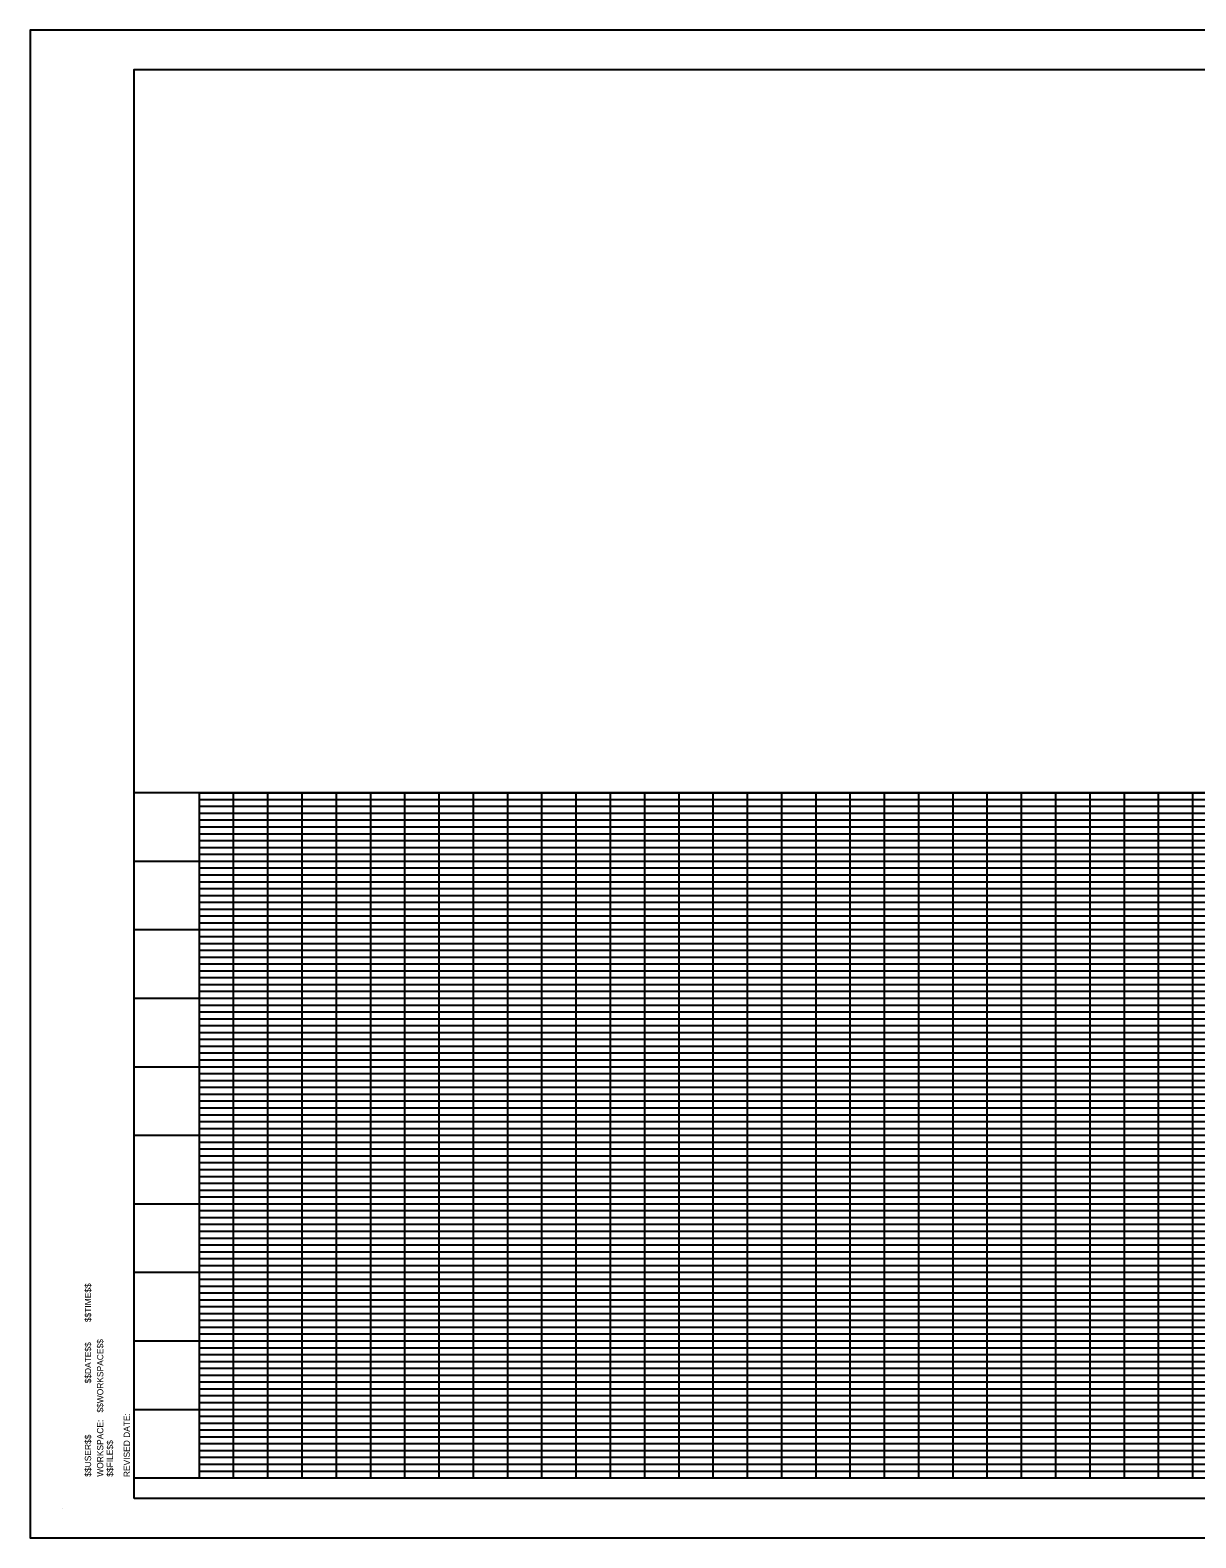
# Model space of a CAD drawing. Extents: x 0 to 17, y -0.6 to 11.2.
# Drawn here: x 0 to 8.51, y 0 to 11 of the extents above; entities that cross this region are included whole.
import ezdxf

# ---------------------------------------------------------------- set-up
doc = ezdxf.new("R2010")
doc.units = 0
for name, color, linetype in [('G-ANNO-TEXT', 7, 'Continuous'), ('G-Border-Paper', 7, 'Continuous'), ('G-Border-Sheet', 7, 'Continuous'), ('G-Grid-Border', 7, 'Continuous'), ('G-Grid-Major', 7, 'Continuous'), ('G-Grid-Minor', 7, 'Continuous'), ('G-No Plot-Border-1', 7, 'Continuous'), ('G-No Plot-Border-2', 7, 'Continuous')]:
    doc.layers.add(name, color=color, linetype=linetype)

msp = doc.modelspace()

# ---------------------------------------------------------------- linework, layer by layer
at = {"layer": 'G-ANNO-TEXT'}
msp.add_line((0.234, 0.214), (0.234, 0.214), dxfattribs=at)
at = {"layer": 'G-Border-Paper'}
msp.add_lwpolyline([(17, 11), (0, 11), (0, 0), (17, 0)], close=True, dxfattribs=at)
at = {"layer": 'G-Border-Sheet'}
for p, q in [((0.758, 10.712), (16.712, 10.712)), ((0.758, 0.288), (0.758, 10.712)), ((16.712, 0.288), (0.758, 0.288))]:
    msp.add_line(p, q, dxfattribs=at)
at = {"layer": 'G-Grid-Border'}
for p, q in [((16.712, 5.435), (0.758, 5.435)), ((16.712, 0.435), (0.758, 0.435))]:
    msp.add_line(p, q, dxfattribs=at)
msp.add_lwpolyline([(1.235, 5.435), (16.235, 5.435), (16.235, 0.435), (1.235, 0.435)], close=True, dxfattribs=at)
at = {"layer": 'G-Grid-Major'}
for p, q in [((1.735, 0.435), (1.735, 5.435)), ((2.235, 0.435), (2.235, 5.435)), ((2.735, 0.435), (2.735, 5.435)), ((3.235, 0.435), (3.235, 5.435)), ((3.735, 0.435), (3.735, 5.435)), ((4.235, 0.435), (4.235, 5.435)), ((4.735, 0.435), (4.735, 5.435)), ((5.235, 0.435), (5.235, 5.435)), ((5.735, 0.435), (5.735, 5.435)), ((6.235, 0.435), (6.235, 5.435)), ((6.735, 0.435), (6.735, 5.435)), ((7.235, 0.435), (7.235, 5.435)), ((7.735, 0.435), (7.735, 5.435)), ((8.235, 0.435), (8.235, 5.435)), ((16.712, 4.935), (0.758, 4.935)), ((16.712, 4.435), (0.758, 4.435)), ((16.712, 3.935), (0.758, 3.935)), ((16.712, 3.435), (0.758, 3.435)), ((16.712, 2.935), (0.758, 2.935)), ((16.712, 2.435), (0.758, 2.435)), ((16.712, 1.935), (0.758, 1.935)), ((16.712, 1.435), (0.758, 1.435)), ((16.712, 0.935), (0.758, 0.935))]:
    msp.add_line(p, q, dxfattribs=at)
msp.add_lwpolyline([(1.235, 5.435), (16.235, 5.435), (16.235, 0.435), (1.235, 0.435)], close=True, dxfattribs=at)
at = {"layer": 'G-Grid-Minor'}
for p, q in [((1.485, 0.435), (1.485, 5.435)), ((1.985, 0.435), (1.985, 5.435)), ((2.485, 0.435), (2.485, 5.435)), ((2.985, 0.435), (2.985, 5.435)), ((3.485, 0.435), (3.485, 5.435)), ((3.985, 0.435), (3.985, 5.435)), ((4.485, 0.435), (4.485, 5.435)), ((4.985, 0.435), (4.985, 5.435)), ((5.485, 0.435), (5.485, 5.435)), ((5.985, 0.435), (5.985, 5.435)), ((6.485, 0.435), (6.485, 5.435)), ((6.985, 0.435), (6.985, 5.435)), ((7.485, 0.435), (7.485, 5.435)), ((7.985, 0.435), (7.985, 5.435)), ((8.485, 0.435), (8.485, 5.435)), ((16.235, 5.385), (1.235, 5.385)), ((16.235, 5.335), (1.235, 5.335)), ((16.235, 5.285), (1.235, 5.285)), ((16.235, 5.235), (1.235, 5.235)), ((16.235, 5.185), (1.235, 5.185)), ((16.235, 5.135), (1.235, 5.135)), ((16.235, 5.085), (1.235, 5.085)), ((16.235, 5.035), (1.235, 5.035)), ((16.235, 4.985), (1.235, 4.985)), ((16.235, 4.885), (1.235, 4.885)), ((16.235, 4.835), (1.235, 4.835)), ((16.235, 4.785), (1.235, 4.785)), ((16.235, 4.735), (1.235, 4.735)), ((16.235, 4.685), (1.235, 4.685)), ((16.235, 4.635), (1.235, 4.635)), ((16.235, 4.585), (1.235, 4.585)), ((16.235, 4.535), (1.235, 4.535)), ((16.235, 4.485), (1.235, 4.485)), ((16.235, 4.385), (1.235, 4.385)), ((16.235, 4.335), (1.235, 4.335)), ((16.235, 4.285), (1.235, 4.285)), ((16.235, 4.235), (1.235, 4.235)), ((16.235, 4.185), (1.235, 4.185)), ((16.235, 4.135), (1.235, 4.135)), ((16.235, 4.085), (1.235, 4.085)), ((16.235, 4.035), (1.235, 4.035)), ((16.235, 3.985), (1.235, 3.985)), ((16.235, 3.885), (1.235, 3.885)), ((16.235, 3.835), (1.235, 3.835)), ((16.235, 3.785), (1.235, 3.785)), ((16.235, 3.735), (1.235, 3.735)), ((16.235, 3.685), (1.235, 3.685)), ((16.235, 3.635), (1.235, 3.635)), ((16.235, 3.585), (1.235, 3.585)), ((16.235, 3.535), (1.235, 3.535)), ((16.235, 3.485), (1.235, 3.485)), ((16.235, 3.385), (1.235, 3.385)), ((16.235, 3.335), (1.235, 3.335)), ((16.235, 3.285), (1.235, 3.285)), ((16.235, 3.235), (1.235, 3.235)), ((16.235, 3.185), (1.235, 3.185)), ((16.235, 3.135), (1.235, 3.135)), ((16.235, 3.085), (1.235, 3.085)), ((16.235, 3.035), (1.235, 3.035)), ((16.235, 2.985), (1.235, 2.985)), ((16.235, 2.885), (1.235, 2.885)), ((16.235, 2.835), (1.235, 2.835)), ((16.235, 2.785), (1.235, 2.785)), ((16.235, 2.735), (1.235, 2.735)), ((16.235, 2.685), (1.235, 2.685)), ((16.235, 2.635), (1.235, 2.635)), ((16.235, 2.585), (1.235, 2.585)), ((16.235, 2.535), (1.235, 2.535)), ((16.235, 2.485), (1.235, 2.485)), ((16.235, 2.385), (1.235, 2.385)), ((16.235, 2.335), (1.235, 2.335)), ((16.235, 2.285), (1.235, 2.285)), ((16.235, 2.235), (1.235, 2.235)), ((16.235, 2.185), (1.235, 2.185)), ((16.235, 2.135), (1.235, 2.135)), ((16.235, 2.085), (1.235, 2.085)), ((16.235, 2.035), (1.235, 2.035)), ((16.235, 1.985), (1.235, 1.985)), ((16.235, 1.885), (1.235, 1.885)), ((16.235, 1.835), (1.235, 1.835)), ((16.235, 1.785), (1.235, 1.785)), ((16.235, 1.735), (1.235, 1.735)), ((16.235, 1.685), (1.235, 1.685)), ((16.235, 1.635), (1.235, 1.635)), ((16.235, 1.585), (1.235, 1.585)), ((16.235, 1.535), (1.235, 1.535)), ((16.235, 1.485), (1.235, 1.485)), ((16.235, 1.385), (1.235, 1.385)), ((16.235, 1.335), (1.235, 1.335)), ((16.235, 1.285), (1.235, 1.285)), ((16.235, 1.235), (1.235, 1.235)), ((16.235, 1.185), (1.235, 1.185)), ((16.235, 1.135), (1.235, 1.135)), ((16.235, 1.085), (1.235, 1.085)), ((16.235, 1.035), (1.235, 1.035)), ((16.235, 0.985), (1.235, 0.985)), ((16.235, 0.885), (1.235, 0.885)), ((16.235, 0.835), (1.235, 0.835)), ((16.235, 0.785), (1.235, 0.785)), ((16.235, 0.735), (1.235, 0.735)), ((16.235, 0.685), (1.235, 0.685)), ((16.235, 0.635), (1.235, 0.635)), ((16.235, 0.585), (1.235, 0.585)), ((16.235, 0.535), (1.235, 0.535)), ((16.235, 0.485), (1.235, 0.485))]:
    msp.add_line(p, q, dxfattribs=at)
at = {"layer": 'G-No Plot-Border-1'}
msp.add_lwpolyline([(0.758, 5.435), (0.758, 10.712), (13.728, 10.712), (13.728, 10.216), (14.721, 10.216), (14.897, 10.216), (15.437, 10.216), (15.437, 8.741), (16.712, 8.741), (16.712, 5.435)], close=True, dxfattribs=at)
at = {"layer": 'G-No Plot-Border-2'}
msp.add_lwpolyline([(0.758, 5.435), (0.758, 10.712), (12.378, 10.712), (12.378, 9.237), (13.728, 9.237), (13.728, 10.216), (14.721, 10.216), (14.897, 10.216), (16.712, 10.216), (16.712, 5.435)], close=True, dxfattribs=at)

# ---------------------------------------------------------------- texts
at = {"layer": 'G-ANNO-TEXT'}
for s, p in [('$$TIME$$', (0.445, 1.574)), ('$$WORKSPACE$$', (0.534, 0.914)), ('$$DATE$$', (0.445, 1.127)), ('REVISED DATE:', (0.728, 0.443)), ('WORKSPACE:', (0.534, 0.446)), ('$$USER$$', (0.445, 0.446)), ('$$FILE$$', (0.605, 0.446))]:
    msp.add_text(s, height=0.0459, rotation=90, dxfattribs=at).set_placement(p)

doc.saveas('drawing.dxf')
